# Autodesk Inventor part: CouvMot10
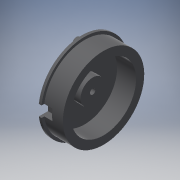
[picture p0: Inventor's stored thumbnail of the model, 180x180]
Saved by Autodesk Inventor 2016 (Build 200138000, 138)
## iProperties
Created: 2013-08
Part Number: CouvMot10
Material: Plastique ABS
Document SubType Name: Modeling
Designer: hilarion
Density: 1.06 g/cm^3
Appearance: Magenta
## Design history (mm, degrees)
node "CouvMot101"
node "CouvMot10"
node "Base1"
